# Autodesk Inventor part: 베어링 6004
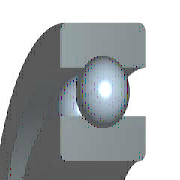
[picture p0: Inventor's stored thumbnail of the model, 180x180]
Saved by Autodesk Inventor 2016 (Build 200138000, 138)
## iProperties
IsCustomPart: 1
Created: 2012-02
Part Number: 베어링 6004
Material: 강철, 연강
Description: 깊은 그루브 볼 베어링
Document SubType Name: Modeling
Standard: KS B 2023
Designer: mduedu
Standards Organization: KS
Language: ko-KR
Size Designation: 6004 - 20 x 42 x 12
Categories: <MemberInstance><Categories><Category DisplayName="샤프트 부품" InternalName="7f7aeb1f-a693-4053-b835-cee3144e0d98" Mnemonic="SHFT"><Category DisplayName="베어링" Inter
Density: 1 g/cm^3
Appearance: 노란색
Author: mduedu
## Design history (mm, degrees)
sketch "스케치" dims "d0" = 5.72 (= -0.26 x WD + 0.26 x BD)
  geometry: L1 (3.14, 15.5)-(8.86, 15.5); L2 (6, 15.5)-(6, 12.64); L3 (6, 15.5)-(6, 18.36); L4 (3.875, 13.586)-(0, 13.586); L5 (0, 10)-(12, 10); L6 (3.875, 17.414)-(0, 17.414); L7 (0, 21)-(12, 21); L8 (12, 10)-(12, 13.586); L9 (8.125, 13.586)-(12, 13.586); L10 (8.125, 17.414)-(12, 17.414); L11 (12, 21)-(12, 17.414); L12 (-1.4, 0)-(8.4, 0) reference; L13 (0, -0.3)-(0, 5.3) reference
  constraints: 22 end point, 4 point on line, 2 collinear, 2 perpendicular, 2 symmetric about line, 1 midpoint, 1 parallel, 14 other
  dimensions: "d9" = 20 diameter of L5 L12 (= WD); "d11" = 42 diameter of L7 L12 (= BD); "d12" = 12 distance between parallel lines of L8 L13 (= KB); "d13" = 27.172 diameter of L9 L12 (= 0.326 x BD + 0.674 x WD)
revolve "본체" stored, may be unused: angle "d6" = 90 deg
revolve "볼" stored, may be unused: angle "d7" = 90 deg
pattern_circular "IDS_ARRAYBALL[SIMPL:T]" dims angle "d3" = 360 deg
body "Solid1"
fillet "모깎기1" dims "d1" = 0.6 (= KRS)
other parameters: "WD" = 20 [user parameter; used in 5 equation terms], "BD" = 42 [user parameter; used in 5 equation terms], "KB" = 12 [user parameter; used in 1 equation term], "KRS" = 0.6 [user parameter; used in 1 equation term], "d4" = 0, "d5" = 0, "d8" = 0, "d14" = 0, "d15" = 0, "BBA" = 0 [user parameter], "BC0" = 5000000 [user parameter], "BC" = 9360000 [user parameter], "BR" = 21 (= 0.5 x BD) [user parameter]
